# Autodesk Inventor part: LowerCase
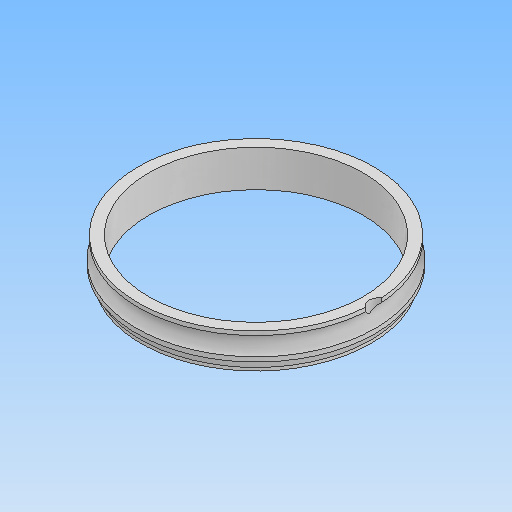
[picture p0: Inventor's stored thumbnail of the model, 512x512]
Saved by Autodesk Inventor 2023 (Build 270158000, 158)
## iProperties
Created: 2024-05
Part Number: LowerCase
Material: 一般
Document SubType Name: Modeling
Designer: kumagai
Density: 1 g/cm^3
Appearance: 既定
Author: kumagai
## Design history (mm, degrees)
derived "CoreSketch.ipt"
  sketch "Vertical"
    geometry: L1 (0, 65.337)-(0, -65.337) reference; L2 (-46.2, 0)-(46.2, 0) reference; L3 (-11, 2)-(11, 2) reference; L4 (11, 2)-(11, -2) reference; L5 (11, -2)-(-11, -2) reference; L6 (-11, -2)-(-11, 2) reference; L7 (11, 2)-(33, 2) reference; L8 (33, 2)-(33, -2) reference; L9 (33, -2)-(11, -2) reference; L10 (11, -2)-(11, 2) reference; L11 (22, 2.772)-(22, -2.683) reference; L12 (-33, 2)-(-11, 2) reference; L13 (-11, 2)-(-11, -2) reference; L14 (-11, -2)-(-33, -2) reference; L15 (-33, -2)-(-33, 2) reference; L16 (-22, 4.087)-(-22, -4.199) reference; L17 (-33, 10)-(-11, 10) reference; L18 (-11, 10)-(-11, 6) reference; L19 (-11, 6)-(-33, 6) reference; L20 (-33, 6)-(-33, 10) reference; L21 (-27.353, 10)-(-16.647, 10) reference; L22 (-16.647, 10)-(-16.647, 16) reference; L23 (-16.647, 16)-(-27.353, 16) reference; L24 (-27.353, 16)-(-27.353, 10) reference; L25 (11, 16)-(33, 16) reference; L26 (33, 16)-(33, 12) reference; L27 (33, 12)-(11, 12) reference; L28 (11, 12)-(11, 16) reference; L29 (16.134, 12)-(27.866, 12) reference; L30 (27.866, 12)-(27.866, 6) reference; L31 (27.866, 6)-(16.134, 6) reference; L32 (16.134, 6)-(16.134, 12) reference; L33 (-22, 18.272)-(-22, 9.031) reference; L34 (22, 22.635)-(22, 12.71) reference; L35 (33, -2)-(35, -2) reference; L36 (35, -2)-(35, 10) reference; L37 (35, 10)-(33, 10) reference; L38 (33, 10)-(33, -2) reference; L39 (0, -4)-(37.5, -4) reference; L40 (40.5, -1)-(40.5, 14) reference; L41 (43.9, -8)-(0, -8) reference; L42 (0, -4)-(0, -8) reference; L43 (35, -2)-(39, -2) reference; L44 (39, -2)-(39, 3.066) reference; L45 (38.45, 8.685)-(41.471, 10.429) reference; L46 (38.45, 10)-(35, 10) reference; L47 (40.5, 9.627)-(41.993, 8.375) reference; L48 (41.55, 3.315)-(40.5, 2.709) reference; L49 (37.5, -4)-(40.5, -1) reference; L50 (-43, 43.294)-(-1, 43.294) reference; L51 (-1, 43.294)-(-1, 26) reference; L52 (-1, 26)-(-43, 26) reference; L53 (-43, 26)-(-43, 43.294) reference; L54 (1, 43.294)-(43, 43.294) reference; L55 (43, 43.294)-(43, 26) reference; L56 (43, 26)-(1, 26) reference; L57 (1, 26)-(1, 43.294) reference; L58 (-22, 45.556)-(-22, 31.232) reference; L59 (22, 47.214)-(22, 32.287) reference; L60 (48, 5.268)-(48, -2.616) reference; L61 (43.6, -11)-(54, -11) reference; L62 (54, -11)-(54, 18) reference; L63 (45.222, -3.461)-(46.5, -2.566) reference; L64 (48, -2.616)-(49.192, -3.808) reference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; A1 r 3.1 centre (40, 6) between (39, 3.066) and (38.45, 8.685) reference; A2 r 3.1 centre (47, -6) between (45.222, -3.461) and (49.192, -3.808) reference; A3 r 3.1 centre (47, 13) between (43.9, 13) and (49, 10.631) reference; 2 further points; 1 other entity
    constraints: 1 other
revolve "回転1" stored, may be unused: angle "d1" = 360 deg
sketch "スケッチ3"
  geometry: L1 (40, 6)-(36.9, 6); L2 (36.9, 6)-(36.9, 10); L3 (36.9, 10)-(40, 10); L4 (40, 10)-(40, 6); L5 (-38.45, 10)-(38.45, 10) reference; 1 further point
  constraints: 8 end point, 2 horizontal, 2 vertical, 1 collinear, 1 horizontal alignment, 1 other
revolve "回転2" sketch "スケッチ3" stored, may be unused: angle "d2" = 90 deg
node "ソリッド1"
